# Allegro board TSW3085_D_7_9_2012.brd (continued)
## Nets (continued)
USB RESET: C50.1 SW2.2 U3.19(RESET)
N27288443: C95.1 J14.2(D-) U3.16(USBDM)
N27288567: FB26.2 R40.1 U3.20(VCC)
N27288614: C97.1 U3.4(VCCIO) U3.17(3V3OUT)
N27288630: C96.1 J14.3(D+) U3.15(USBDP)
N27836198: C152.1 C153.1 F2.2 FB20.2 Q1.4(S4) Q1.7(S7)
N28086696: C133.1 C163.1 C169.1 C234.1 C240.1 FB31.3 TP20.1(TP) U12.1(EN) U12.2(IN) U13.1(IN) U13.3(EN) U22.1(IN) U22.3(EN)
N28167010: C184.1 C197.2 L3.1 R277.1
N28167020: C184.2 C192.1 L4.1 R278.1
N28168739: C200.2 C205.1 L1.1 R280.1
N28168741: C205.2 C220.1 L2.1 R279.1
N28168902: C206.2 C221.1 R279.2 R303.1
N28168904: C206.1 C217.2 R280.2 R302.1
N30175128: C146.1 C244.1 C245.1 FB34.1 R128.2 R257.2 U13.5(OUT)
N30185572: C149.1 C246.1 C247.1 R127.1 R221.2 U22.5(OUT)
N31066293: C186.1 C198.2 R277.2 R296.1
N31066982: C186.2 C193.1 R278.2 R297.1
N33713354: C35.1 R43.1 R133.1
N33713380: C34.1 R43.2
N33713396: R133.2 U1.A1(LPF)
N33713852: R44.2 R45.1
N33713873: R44.1 U1.A33(BIASJ)
N33714300: JP3.2(PIN2) U1.B40(SLEEP)
N33806169: C259.1 R313.1
N33840412: C252.1 C253.1 C288.1 C290.1 R88.1 R118.2 U23.24(VCC_LO)
N33892115: C254.1 C255.1 C289.1 C291.1 R96.2 R115.2 U23.18(VCC_MOD)
N33970284: R12.2 R221.1 U22.4(NR/FB)
N33977043: R10.2 R257.1 U13.4(NR/FB)
N34062669: C132.2 C259.2 R174.1
N34111815: C113.1 U14.6(NR)
N34113396: R157.1 R159.2 U14.3(FB/SNS)
N34123238: FB35.1 R127.2 R128.1
N34242338: C119.1 U18.6(NR)
N34242397: R171.2 R176.1 U18.3(FB/SNS)
N34261747: R107.2 U7.3(\\P\/S)
N34261766: C175.1 C176.1 FB23.1 U7.2(VDD)
N34261843: C110.1 C251.1 C256.1 L5.1 R293.2
N34261894: R108.2 U7.4(A0) U7.22(A1)
N34318237: C107.1 C127.1 U16.42(CPOUT2)
N34318365: C59.1 U16.11(LDOBYP1)
N34318369: C52.1 U16.12(LDOBYP2)
N34318504: D1.1(ANODE) R8.1
N34318582: R11.2 U16.33(STATUS_LD)
N34318594: R9.2 U16.63(STATUS_CLKIN1)
N34318598: R8.2 U16.62(STATUS_CLKIN0)
N34318724: FB2.2 JP4.2(PIN2)
N34318773: C77.2 U16.37(OSCINN)
N34318798: C88.1 C102.1 C181.1 FB10.1 U16.17(VCC2) U16.18(VCC3)
N34318866: C87.1 C179.1 FB19.1 U16.64(VCC13)
N34318908: R274.2 Y1.2(\\E\D\)
N34318943: R70.2 R72.1 SJP5.2(PIN2) U26.1(CLKIN)
N34319037: C302.1 C303.1 FB8.1 U26.2(OE) U26.6(VDD3.3V)
N34319101: R61.2 R62.2 R273.2 Y1.1(VC)
N34319133: C63.1 C64.1 C65.1 FB2.1 R61.1 Y1.6(VDD)
N34319167: R54.1 Y1.4(OUT)
N34319169: R54.2 SJP5.3(PIN3)
N34319278: D5.1(ANODE) R9.1
N34319280: D4.1(ANODE) R11.1
N34319320: C89.1 C90.1 C99.1 C180.1 FB18.1 U16.47(VCC10) U16.52(VCC11) U16.57(VCC12)
N34319417: C86.1 C298.1 FB12.1 U16.41(VCC8)
N34319628: C78.2 U16.26(CLKIN1N/FBCLKINN/FINN)
N34337938: D3.1(ANODE) R40.2
N34338940: C8.1 FB26.1 U6.5(VOUT)
N34339153: SJP3.2(PIN2) U6.3(ON/O\F\F\)
N34340024: J14.4(ID) R117.1
N34341306: U4.35(IO14) U5.2(SO)
N34341363: R19.1 U3.3(D2) U4.43(IO2)
N34341376: R20.1 U3.11(D3) U4.18(IO26)
N34341390: R22.1 U3.9(D5) U4.19(IO25)
N34341426: R21.1 U3.2(D4) U4.44(IO3)
N34341471: R120.2 U5.7(H\O\L\D\)
N34341475: U4.34(IO15) U5.1(C\S\)
N34341497: SJP2.2(PIN2) U5.3(W\P\)
N34341585: R23.1 U3.10(D6) U4.23(IO21)
N34341705: R24.1 U3.6(D7) U4.22(IO22)
N34341779: R16.1 U3.1(D0) U4.2(IO4)
N34341783: R17.1 U3.5(D1) U4.42(IO1)
N34538813: SJP4.2(PIN2) U4.37(INPUT/GCLK1)
N34674333: C166.1 C167.1 FB30.1 L26.2 R150.2
N34674399: C165.1 FB31.1 L25.2 R148.2 U11.4(FB1)
N34674443: C166.2 R150.1 R153.2 U11.1(ADJ2)
N34674591: L25.1 U11.6(SW1)
N34674628: C145.1 C164.1 FB22.1 FB24.1 U12.4(OUT)
N34674653: R148.1 R151.2 U11.5(DEF_1)
N34674671: C162.1 U12.5(NR/FB)
N34674884: C299.2 R95.2 R104.1 U2.3(FB)
N34674886: C299.1 C305.1 FB28.1 L7.2 R104.2
N34674940: C215.1 U15.5(NR/FB)
N34674946: C306.1 C307.1 FB28.3 U15.1(EN) U15.2(IN)
N34708918: J13.175 R175.1
N34708920: J13.177 R177.1
N34708959: J13.21 R6.1
N34714738: J13.38 R25.2
N34714741: J13.40 R26.2
N34722561: J13.50 R28.2
N34722570: J13.52 R27.2
N34728902: J13.47 R1.1
N34729206: J13.51 R2.1
N34729215: J13.53 R3.1
N34729224: J13.59 R4.1
N34783131: C7.1 U6.4(BYP)
N34841492: Q1.3(G3) U21.4(GATE)
N278362830: D2.1(ANODE) R143.1
N343181311: C127.2 R89.1
N343181471: C177.2 R90.1
N346744130: L26.1 U11.10(SW2)

Pads without a net: J13 5 6 11 12 13 14 15 16 17 18 19 20 22 23 24 25 29 30 31 32 33 34 35 36 37 39 41 42 43 44 45 46 54 56 58 60 62 64 68 70 74 76 80 82 86 88 92 94 98 100 104 106 110 112 122 124 128 130 134 136 140 142 146 148 152 154 158 160 164 166 169 171; J14 1; J15 6 7 8; NOREF#22 1; NOREF#33 1; NOREF#43 1; NOREF#45 1; NOREF#46 1; NOREF#47 1; U1 A44; U3 8 12 13 14 22 23 24 27 28; U7 1 26 27 28 29 30 31 32; U16 3 4 5 7 8 9 13 14 21 22 31 32 39 40 49 50 51 55 56 58 59 60 61; U21 1 3; U26 3; Y1 5

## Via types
v1: diameter 0.508, hole 0.254, TOP to BOTTOM, 1602 vias
v2: diameter 0.254, hole 0.203, TOP to BOTTOM, 151 vias
v3: diameter 0.61, hole 0.305, TOP to BOTTOM, 221 vias
v4: diameter 0.914, hole 0.254, TOP to BOTTOM, 2 vias
v5: diameter 0.254, hole 0.152, TOP to BOTTOM, 42 vias
v6: diameter 0.559, hole 0.305, TOP to BOTTOM, 93 vias
v7: diameter 0.406, hole 0.203, TOP to BOTTOM, 39 vias
v8: diameter 0.762, hole 0.381, TOP to BOTTOM, 8 vias

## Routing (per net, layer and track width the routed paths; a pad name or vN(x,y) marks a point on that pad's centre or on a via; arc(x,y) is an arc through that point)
6VIN: length 5.3
  BOTTOM w0.254: J13.2 v1(9.88,100.99) ; J13.4 v1(12.57,100.49) ; J13.1 v1(3.83,100.99) ; J13.3 v1(6.45,100.49)
  vias: v1(2.92,102.88) v1(2.92,101.61) v1(3.91,102.97) v1(4.42,102.46) v1(5.05,101.96) v1(9.91,102.88) v1(10.77,102.97) v1(11.38,102.46) v1(12.04,102.08) v1(13.08,103.52) v1(15.62,106.69) v1(15.62,104.15) v1(16.89,107.33) v1(16.89,105.42) v1(16.89,103.52) v1(18.16,106.69) v1(18.16,104.15)
+1.2VCLK: length 0.5
  TOP w0.102: U1.A4 44,69.41
  TOP w0.152: 44,69.41 43.89,69.52 v2(43.89,69.65)
  vias: v1(65.66,30.23) v1(65.66,29.46) v1(65.91,28.57) v1(66.42,30.86) v1(66.42,29.97) v1(66.42,29.21) v1(66.8,28.57) v1(67.18,30.86) v1(67.18,29.97) v1(67.18,29.21) v2(41.27,75.06) v2(41.27,74.42) v2(41.78,74.55) v2(42.29,75.06) v2(42.29,74.55)
+1.2VD: length 6.9
  TOP w0.102: v5(40.87,70.43) 41,70.3 U1.A9 ; 41,59.54 41.02,59.52 41.02,59.23 ; U1.A25 41,60.5 ; U1.A28 42.8,60.5 ; 42.8,59.59 42.8,59.23
  TOP w0.127: 42.8,60.5 42.8,60.3
  TOP w0.152: v5(42.65,69.62) 42.65,69.35 U1.A6 ; 42.8,60.3 42.8,59.59 ; 41.02,59.23 41.02,58.93 40.82,58.72 v2(40.77,58.72) ; 41,60.5 41,59.54 ; v2(42.88,58.72) 42.8,58.85 42.8,59.23
  BOTTOM w0.254: C26.1 41,70.31 v5(40.87,70.43)
  vias: v1(36.14,25.6) v1(36.2,24.51) v1(36.58,23.88) v1(36.83,25.91) v1(36.83,25.27) v1(37.47,25.91) v1(37.47,25.27) v1(37.54,24.77) v1(37.8,24.26) v1(38.05,23.72) v1(38.1,25.91) v1(38.1,25.27) v1(38.86,75.06) v1(39.24,74.55) v1(39.88,74.93)
+1.2VDAC: length 2.1
  TOP w0.102: U1.A39 v5(47.98,64.95)
  BOTTOM w0.102: C17.1 47.09,67.35 v5(47.1,67.35)
  BOTTOM w0.254: C36.1 43.71,68.3 v5(43.71,68.38) v5(43.71,68.66) ; v5(47.1,62.55) 47.09,62.54 C19.1
  vias: v1(59.05,27.56) v1(59.05,26.8) v1(59.31,26.04) v1(59.82,27.56) v1(59.82,26.8) v1(60.07,26.04) v1(60.58,28.07) v1(60.58,27.18) v2(49.06,61.39) v2(49.06,60.38) v2(49.57,60.88) v2(50.08,61.39) v2(50.08,60.38)
+3.3V_MOD1:
  vias: v1(74.3,26.29) v1(74.68,26.92) v1(75.06,26.29) v1(75.44,26.92) v1(75.82,26.29) v1(76.2,26.92) v1(76.58,26.29) v1(76.96,26.92) v1(77.34,26.29) v1(77.6,65.05) v1(77.6,64.41) v1(77.6,63.65) v1(78.23,65.05) v1(78.23,64.41) v1(78.23,63.65)
+3.3V_MOD2:
  vias: v1(79.63,26.29) v1(80.01,26.92) v1(80.39,26.29) v1(80.77,26.92) v1(81.15,26.29) v1(81.53,26.92) v1(81.91,26.29) v1(82.3,26.92) v1(82.68,26.29) v1(102.64,69.62) v1(102.64,68.99) v1(103.4,70.26) v1(103.4,69.62) v1(103.4,68.99)
+3.3VA: length 1
  BOTTOM w0.305: C22.1 47.09,64.49 v5(47.09,64.35) v5(47.09,63.75) ; v5(47.09,65.54) 47.04,65.49 C20.1
  vias: v1(58.1,76.96) v2(46.42,62.25) v2(49.97,69.37) v2(49.97,68.35) v2(50.48,68.86) v2(50.99,69.37) v2(50.99,68.35) v3(48.26,17.91) v3(48.26,17.14) v3(48.26,16.26) v3(48.26,15.37) v3(49.28,17.91) v3(49.28,17.14) v3(49.28,16.26) v3(49.28,15.37) v5(47.09,66.75) v5(47.09,66.14) v5(47.09,63.14)
+3.3VCLK: length 2.6
  TOP w0.508: v3(76.71,124.33) v1(77.52,124.33)
  BOTTOM w0.508: v1(89.15,110.06) 89.15,110.39 v1(89.32,110.55) U4.29
  vias: v1(34.72,101.57) v1(35.28,101.45) v1(37.77,102.11) v1(38.33,102.67) v1(42.38,101.4) v1(43.25,94.81) v1(43.36,94.16) v1(43.69,116.36) v1(43.78,116.98) v1(48.2,110.05) v1(48.89,101.71) v1(49.98,108.27) v1(51.02,107.21) v1(51.07,103.84) v1(52.5,112.19) v1(52.95,104.21) v1(53.06,112.09) v1(53.54,104.14) v1(73.03,119.38) v1(82.89,106.17) v1(84.58,106.17) v1(85.85,102.23) v1(86.12,100.55) v1(88.14,117.35) v1(88.65,115.15) v1(89.15,117.35) v1(92.46,104.52) v1(93.6,117.48) v1(94.14,104.57) v1(97.54,124.08) v1(100.33,126.62) v1(100.71,110.74) v1(102.87,126.62) v1(105.41,126.62) v1(109.35,126.62) v2(42.7,101.73) v2(47.9,109.75) v2(48.64,102.01) v2(49.68,108) v2(50.75,106.93) v2(50.75,104.14) v3(90.32,117.3) v3(91.29,116.69) v3(99.95,107.44) v3(100.46,108.2) v3(100.56,109.6) v3(100.58,105.54) v3(100.58,104.78)
+3.3VD: length 10.7
  BOTTOM w0.152: C41.1 v5(42.49,68.66)
  BOTTOM w0.254: v2(38.5,64.9) 38.81,64.9 C43.1 ; C42.1 v2(42.5,61.25)
  BOTTOM w0.508: R46.2 v1(44.83,38.23)
  BOTTOM w0.762: JP3.1 JP2.1
  vias: v1(42.7,29.97) v1(42.7,29.29) v1(42.7,28.6) v1(42.7,27.89) v1(42.7,27.2) v1(43.31,30) v1(43.31,29.31) v1(43.31,28.63) v1(43.31,27.91) v1(43.31,27.23) v5(42.49,68.35)
+3.3VRF:
  vias: v1(77.72,17.78) v1(78.36,16.51) v1(78.36,15.24) v1(78.36,13.97) v1(78.36,12.7) v1(78.99,17.78) v1(79.63,16.51) v1(79.63,15.24) v1(79.63,13.97) v1(80.26,17.78) v1(81.53,17.78) v1(82.8,17.78) v1(107.62,55.4) v1(110.18,50.57) v1(113.18,55.4)
+3.6V: length 3
  TOP w0.305: L7.1 109.74,109.87 U2.1
+5V_MOD1:
  vias: v1(87,26.42) v1(87.38,27.05) v1(87.63,26.42) v1(88.01,27.05) v1(88.27,26.42) v1(88.65,27.05) v1(88.9,26.42) v1(89.28,27.05) v1(89.53,26.42) v1(91.19,59.74) v1(91.29,70) v1(94.21,59.71) v1(94.36,70)
+5V_MOD2:
  vias: v1(74.42,67.46) v1(74.42,66.83) v1(75.06,67.46) v1(75.06,66.83) v1(75.69,67.46) v1(75.69,66.83) v1(92.33,26.42) v1(92.71,27.05) v1(92.96,26.42) v1(93.34,27.05) v1(93.6,26.42) v1(93.98,27.05) v1(94.23,26.42) v1(94.62,27.05) v1(94.87,26.42) v1(102.36,75.08) v1(102.36,74.45) v1(102.36,73.81) v1(103,75.08) v1(103,74.45) v1(103,73.81)
+5VA_MOD: length 0.9
  TOP w0.305: 86.61,12.19 86.05,11.63 U18.2
  vias: v1(88.77,17.91) v1(88.77,16.89) v1(89.92,17.91) v1(89.92,16.89) v1(91.06,17.91) v1(91.06,16.89) v1(92.2,17.91) v1(92.2,16.89) v1(93.34,17.91) v1(93.34,16.89) v1(94.62,17.91) v1(94.62,16.89) v1(105.97,50.04)
+6V: length 9.4
  TOP w0.305: 36.96,15.92 C237.1 ; 36.96,15.92 v2(38.43,15.92) ; 36.96,15.92 36.96,15.62 37.17,15.42 U11.3 ; v3(115.72,109.04) 115.54,109.22 v2(115.07,109.22) ; v1(84.43,8.08) 84.75,8.4 U18.5 ; 76.96,7.87 76.53,8.31 U14.7 ; 86.49,7.87 86.05,8.31 U18.7 ; U14.5 75.23,8.55 v1(74.8,8.13) ; v1(42.42,14.91) 42.41,14.92 U11.7
  TOP w0.508: C172.1 v1(83.06,7.75)
  vias: v1(32.74,16.15) v1(32.77,15.62) v1(33.48,16.59) v1(33.66,15.62) v1(34.62,16.21) v1(34.67,15.62) v1(35.69,15.62) v1(35.76,16.1) v1(36.7,15.62) v1(36.78,16.13) v1(72.9,7.24) v1(73.41,6.48) v1(79.04,7.49) v1(79.04,6.88) v1(79.65,7.49) v1(79.65,6.91) v1(88.9,7.47) v1(88.9,6.86) v1(89.51,7.47) v1(89.51,6.88) v1(93.32,11.29) v1(96.74,12.88) v1(96.74,11.87) v1(103.78,118.03) v1(106.81,116.21) v2(38.43,15.42) v2(41.45,14.91) v2(41.48,15.93) v2(115.07,108.57) v3(94.61,11.82) v3(95.54,11.15) v3(105.66,112.52) v3(107.06,118.75) v3(107.06,117.48) v3(107.7,118.11) v3(108.61,118.77) v3(108.64,117.45) v3(116.08,108.48) v3(116.64,108.92) v3(117.3,108.51)
GNDA: length 163.4
  TOP w0.152: v1(63.12,28.83) C238.2 v1(63.88,28.83) ; U3.7 97.21,117.93 v1(97.16,117.98)
  TOP w0.254: U1.B33 46.45,63.11 v2(46.43,63.04) 46.45,63.08 U1.B32 ; v1(95.66,65.91) 95.47,65.72 95.38,65.72 95.36,65.7 U23.17 ; U23.8 92.01,62.09 v1(91.82,61.9) ; U1.B39 v2(46.45,66.91) ; U1.B38 v2(46.45,66.28)
  TOP w0.305: v1(93.52,64.19) 94.01,63.7 ; v1(93.52,64.19) 93.51,64.17 U23.11 ; v1(93.52,64.19) 93.53,64.2 U23.14 ; 94.01,63.7 U23.13 ; 94.01,63.7 U23.12 ; v1(84.4,12.17) 84.75,11.82 U18.4 ; v1(113.92,109.8) 113.98,109.87 U2.6 ; v2(112.77,109.22) 113.89,109.22 v1(113.92,109.25) ; v1(93.52,65.71) 93.51,65.72 U23.20 ; v1(93.52,65.71) 93.53,65.7 U23.17 ; v1(93.52,65.71) 93.98,66.17 93.98,66.59 94.01,66.62 U23.19 ; v1(81.66,62.89) 81.08,63.47 R313.2 ; v5(93.52,62.71) 93.52,62.1 v1(93.73,61.9) ; v1(61.98,10.41) U13.2 v1(60.58,10.41) ; U11.8 v3(40.36,15.42) v1(40.33,15.42) U11.11 ; v1(75.5,10.66) 75.23,10.93 U14.4 75.23,11.9 v1(74.93,12.19) ; U22.2 v1(68.83,10.29) ; U23.23 92.01,65.72 v1(92,65.71) 91.99,65.7 U23.2 ; U23.5 91.99,64.2 v1(92,64.19) 92.01,64.17 U23.8 ; U23.15 93.53,64.7 v1(93.52,64.69)
  TOP w0.381: v1(70.53,123.28) U26.4 v1(73.26,123.28) ; v1(99.75,14.68) U21.2 v1(98.65,14.66)
  TOP w0.508: C254.2 v1(98.02,67.74) ; v1(101.71,68.24) v3(100.84,68.24) v1(100.84,67.23) ; v1(60.71,15.11) v3(61.29,15.11) C244.2 ; D5.2 v1(27.33,100.13) ; C196.1 v1(62.59,73.43) ; C245.2 v1(61.72,16.41) ; v1(66.29,11.3) v3(66.29,10.72) C240.2 ; C170.2 v1(56.52,25.53) ; v3(68.3,14.86) v1(67.69,14.86) ; R200.2 v1(94.21,56.67) ; C191.2 v1(62.59,70.41) ; v1(60.2,13.34) v3(60.93,13.34) C146.2 v1(60.96,12.47) ; C174.2 v1(84.96,14.61) ; D4.2 v1(27.36,102.41) ; R6.2 v1(7.34,97.66) ; v1(57.02,26.8) C243.2 ; C149.2 v1(67.18,13.08) ; C199.1 v1(73.76,56.84) ; v1(70.36,6.86) v3(71.12,6.86) ; C171.2 v1(74.17,16.64) ; C172.2 v1(83.06,9.78) ; D1.2 v1(27.36,97.84) ; v3(75.41,14.99) v1(74.8,14.99) ; C120.2 v1(89.28,10.54) ; R198.2 v1(94.34,73.05) ; v1(54.58,12.5) v3(54.58,13.39) U12.3 v1(54.58,14.4) ; C194.2 v1(73.79,70.43) ; v1(78.77,9.8) v3(79.35,9.8) C114.2 v1(79.38,10.41) ; v1(74.3,13.21) v1(74.3,13.72) ; R12.1 v1(72.01,8.61) ; C167.2 v3(38.4,19.3) ; C169.2 v3(59.31,10.72) v1(59.31,11.3) ; D2.2 v1(90.65,7.16) ; C255.2 v1(97.03,67.77) ; C173.2 v1(84.28,16.38) ; C233.2 v1(34.62,25.6) ; C218.2 v1(73.79,59.89) ; C219.2 v1(62.59,59.87) ; C147.2 v1(55.88,23.75)
  L2_GND w0.305: 93.73,41.48 93.73,41.15 93.47,40.89
  BOTTOM w0.102: 45.92,68.02 C48.2 ; v6(45.3,67.4) 45.21,67.48 ; 46.45,66.18 v2(46.45,66.28)
  BOTTOM w0.152: R137.1 97.14,61.71 v1(97.28,61.85)
  BOTTOM w0.254: C21.2 46.36,66.8 45.97,66.8 45.72,66.55 45.45,66.55 v6(45.3,66.4) 45.57,66.12 46.42,66.12 C23.2 46.45,66.18 ; C49.2 v5(45.21,67.89) 45.21,67.48 ; v6(44.3,67.4) 44.06,67.16 C36.2 ; C42.2 41.74,61.96 v6(41.3,62.4) ; v6(40.3,65.4) 40.23,65.33 40.23,65.1 40.01,64.92 C43.2 ; v6(45.3,67.4) 45.92,68.02
  BOTTOM w0.305: 12.95,60.07 12.87,59.98 J13.126 10.2,59.98 v1(9.78,59.56) ; v1(9.91,75.18) 10.2,75.48 J13.84 13.16,75.48 13.21,75.44 ; J13.83 v1(4.16,75.48) ; J13.101 v1(4.12,70.98) ; 12.95,58.67 12.76,58.48 J13.132 10.09,58.48 v1(9.53,57.91) ; 13.21,77.09 13.1,76.98 J13.78 9.67,76.98 9.4,76.71 ; v1(9.65,51.05) 9.73,50.98 J13.162 12.91,50.98 12.95,50.93 ; v6(41.3,67.4) 41,67.7 C26.2 ; 12.95,79.88 12.85,79.98 J13.66 10.13,79.98 v1(9.78,79.63) ; J13.7 v1(4.07,99.49) ; J13.89 v1(4.1,73.98) ; v6(45.3,63.4) 45.71,63.8 C5.2 ; v6(45.3,65.4) 45.37,65.33 C20.2 ; C41.2 42.49,67.59 v6(42.3,67.4) ; J13.161 3.94,50.98 3.43,50.47 v1(3.43,50.42) ; J13.65 v1(4.11,79.98) ; 10.03,55.5 10.05,55.48 J13.144 12.81,55.48 12.83,55.5 ; v6(45.3,62.4) 45.47,62.23 C6.2 ; J13.137 v1(4.1,56.98) ; J13.149 v1(4.04,53.98) ; J13.77 v1(4.17,76.98) ; J13.9 v1(6.28,98.99) ; 9.4,56.77 9.61,56.98 J13.138 12.62,56.98 v1(12.7,56.9) ; 12.83,53.98 12.82,53.98 J13.150 10.28,53.98 v1(9.4,54.86) ; v6(45.3,64.4) 45.44,64.54 C22.2 ; J13.156 12.34,52.48 v1(13.08,53.21) ; 11.3,45.72 11.35,45.77 J13.180 v1(10.25,46.47) ; 12.83,68.58 12.22,67.98 J13.114 v1(10.32,67.98) ; J13.71 v1(4.14,78.48) ; v1(13.08,49.66) 12.9,49.47 J13.168 9.85,49.47 9.78,49.4 ; J13.143 v1(4.07,55.48) ; J13.174 v1(10.29,47.97) ; J13.119 v1(4.12,66.47) ; 9.4,78.11 9.78,78.48 J13.72 13.71,78.48 13.84,78.61 ; J13.8 v1(12.48,99.49) ; 9.78,69.47 9.79,69.48 J13.108 13.07,69.48 13.08,69.47 ; J13.107 v1(4.13,69.48) ; J13.179 v1(4.16,46.47) ; J13.10 v1(10.26,98.99) ; J13.131 v1(4.05,58.48) ; v1(12.95,73.91) 12.89,73.98 J13.90 ; J13.113 v1(4.07,67.98) ; 9.78,70.99 9.79,70.98 J13.102 12.3,70.98 v1(12.83,71.5) 12.83,71.94 12.28,72.48 J13.96 9.99,72.48 9.78,72.26 ; J13.120 10.85,66.47 10.59,66.22 v1(10.59,65.79) ; J13.167 v1(4.15,49.47) ; J13.95 v1(4.13,72.48) ; J13.125 v1(4.03,59.98) ; J13.155 v1(4.09,52.48) ; J13.173 v1(4.12,47.97)
  BOTTOM w0.508: C47.2 v1(44.32,36.7) ; R45.2 v1(46.1,53.57) ; C154.2 v1(97.76,12.37) v1(97.76,12.88) ; C7.2 C8.2 ; C152.2 v1(90.35,4.62)
  vias: v1(0.84,37.72) v1(0.89,84.07) v1(0.89,81.79) v1(0.89,77.98) v1(0.89,74.17) v1(0.89,70.36) v1(0.89,66.55) v1(0.89,62.74) v1(0.89,58.93) v1(0.89,55.12) v1(0.89,51.31) v1(0.89,47.5) v1(0.94,41.68) v1(1.02,110.49) v1(1.02,106.68) v1(1.02,102.87) v1(1.02,99.06) v1(1.02,95.25) v1(1.02,91.44) v1(1.02,87.63) v1(1.02,44.96) v1(3.18,108.59) v1(3.76,105) v1(3.81,112.4) v1(3.81,104.01) v1(4.45,34.92) v1(5.08,113.67) v1(5.08,105.03) v1(5.08,104.01) v1(5.08,39.37) v1(5.33,107.32) v1(5.89,84.23) v1(5.92,82.55) v1(6.1,63.5) v1(7.62,111.76) v1(8,59.26) v1(8.23,103.02) v1(8.26,102.11) v1(8.26,101.24) v1(8.23,98.81) v1(8.26,97.84) v1(8.26,96.84) v1(8.26,95.96) v1(8.26,92.46) v1(8.26,91.49) v1(8.26,90.49) v1(8.26,89.54) v1(8.26,88.47) v1(8.26,86.16) v1(8.26,85.22) v1(8.26,84.3) v1(8.26,82.5) v1(8.26,81.25) v1(8.26,78.84) v1(8.26,76.25) v1(8.26,74.83) v1(8.26,69.52) v1(8.26,66.17) v1(8.26,65.21) v1(8.26,64.29) v1(8.26,57.53) v1(8.26,55.88) v1(8.26,51.51) v1(8.26,50.67) v1(8.26,48.59) v1(8.26,45.85) v1(8.26,45.21) v1(8.23,44.27) v1(8.26,34.92) v1(8.28,71.48) v1(8.28,61.98) v1(8.28,61.26) v1(9.53,44.58) v1(10.74,105) v1(10.74,103.99) v1(11.02,29.77) v1(11.43,118.11) v1(11.38,104.5) v1(11.43,44.58) v1(12.01,105) v1(12.01,103.99) v1(12.07,34.92) v1(12.52,98.22) v1(12.7,111.76) v1(12.73,87.43) v1(12.7,39.37) v1(13.21,44.45) v1(13.34,116.21) v1(13.97,41.27) v1(14.61,114.94) v1(15.11,32) v1(15.24,118.11) v1(15.24,40.01) v1(15.49,29.77) v1(15.88,116.21) v1(15.88,34.92) v1(16.21,86.49) v1(16.51,41.27) v1(17.42,89.71) v1(17.78,111.76) v1(17.78,39.37) v1(19.05,118.11) v1(19.69,87.63) v1(19.69,85.09) v1(19.69,34.92) v1(20.04,29.74) v1(20.95,86.36) v1(21.59,108.59) v1(21.59,106.05) v1(22.23,87.63) v1(22.23,85.09) v1(22.23,45.09) v1(22.86,111.76) v1(22.86,107.32) v1(22.86,39.37) v1(23.5,43.81) v1(23.5,34.92) v1(23.75,94.67) v1(24.13,108.59) v1(24.13,106.05) v1(24.13,40.64) v1(24.61,29.77) v1(24.77,92.71) v1(24.77,90.17) v1(24.77,45.09) v1(25.4,118.11) v1(25.4,39.37) v1(26.04,110.49) v1(26.04,91.44) v1(26.67,40.64) v1(27.3,132.08) v1(27.3,128.27) v1(27.3,124.46) v1(27.3,120.65) v1(27.3,116.84) v1(27.3,109.22) v1(27.3,92.71) v1(27.3,90.17) v1(27.3,34.92) v1(27.3,31.75) v1(27.3,27.94) v1(27.3,24.13) v1(27.3,20.32) v1(27.3,15.88) v1(27.3,13.97) v1(27.3,10.8) v1(27.3,7.62) v1(27.3,5.71) v1(27.94,130.81) v1(27.94,117.48) v1(27.94,111.76) v1(28.42,39.4) v1(28.57,110.49) v1(29.21,129.54) v1(29.21,116.21) v1(29.21,29.84) v1(29.21,27.3) v1(29.21,9.53) v1(29.21,6.99) v1(29.59,90.04) v1(29.59,87.5) v1(29.85,22.86) v1(29.85,20.32) v1(30.48,130.81) v1(30.48,117.48) v1(30.48,28.57) v1(30.48,8.25) v1(30.86,88.77) v1(31.04,41.33) v1(31.12,34.92) v1(31.12,32.38) v1(31.12,21.59) v1(31.75,125.73) v1(31.75,123.19) v1(31.75,29.84) v1(31.75,27.3) v1(31.75,13.97) v1(31.75,11.43) v1(31.75,9.53) v1(31.75,6.99) v1(31.75,0.64) v1(32.13,116.21) v1(32.13,114.17) v1(32.13,90.04) v1(32.13,87.5) v1(32.38,117.98) v1(32.38,33.66) v1(32.38,22.86) v1(32.38,20.32) v1(32.64,107.95) v1(32.64,40.39) v1(33.02,124.46) v1(33.02,46.35) v1(33.02,12.7) v1(33.66,34.92) v1(33.66,32.38) v1(33.78,42.04) v1(34.16,119.76) v1(34.29,125.73) v1(34.29,123.19) v1(34.29,45.09) v1(34.29,13.97) v1(34.29,11.43) v1(34.54,97.28) v1(34.62,17.78) v1(34.67,94.49) v1(34.8,109.86) v1(34.92,132.72) v1(34.93,105.33) v1(35.05,99.06) v1(35.36,43.54) v1(35.56,46.35) v1(35.74,17.12) v1(35.81,121.29) v1(35.81,112.78) v1(36.2,0.64) v1(36.45,107.82) v1(36.58,134.49) v1(36.58,131.06) v1(36.68,11.48) v1(36.78,17.12) v1(36.83,4.45) v1(36.83,1.91) v1(37.09,107.49) v1(37.34,122.81) v1(37.34,97.28) v1(37.34,94.62) v1(37.44,45.47) v1(37.95,19.86) v1(37.95,18.72) v1(37.97,119.76) v1(38.1,112.9) v1(38.07,21.36) v1(38.1,3.17) v1(38.73,124.21) v1(38.73,77.72) v1(38.84,19.86) v1(38.84,18.72) v1(39.24,115.57) v1(39.24,103) v1(39.27,77.08) v1(39.37,4.45) v1(39.37,1.91) v1(39.53,16.22) v1(39.53,15.42) v1(39.53,14.62) v1(39.62,121.41) v1(39.75,76.58) v1(40.01,49.53) v1(40.01,46.99) v1(40.01,41.91) v1(40.14,111.03) v1(40.33,16.22) v1(40.33,14.62) v1(40.39,125.86) v1(40.39,115.06) v1(40.64,0.64) v1(40.7,98.49) v1(40.77,133.98) v1(40.79,96.93) v1(41.15,131.57) v1(41.15,122.94) v1(41.27,129.29) v1(41.27,127) v1(41.27,76.58) v1(41.27,48.26) v1(41.4,97.28) v1(41.66,113.79) v1(41.81,77.08) v1(42.15,98.44) v1(42.33,113.2) v1(42.29,77.6) v1(42.55,121.29) v1(42.55,49.53) v1(42.55,46.99) v1(42.55,45.09) v1(42.67,133.86) v1(42.93,124.59) v1(43.81,120.02) v1(43.94,131.57) v1(43.94,130.05) v1(43.94,128.27) v1(43.94,126.11) v1(44.35,96.24) v1(45.09,127) v1(45.09,124.46) v1(45.09,121.29) v1(45.09,118.75) v1(45.21,133.98) v1(45.72,86.61) v1(45.72,84.07) v1(45.72,0.64) v1(45.8,33.59) v1(46.36,125.73) v1(46.94,33.59) v1(46.97,96.38) v1(46.99,85.34) v1(47.12,108.97) v1(47.35,9.45) v1(47.5,123.06) v1(47.5,120.14) v1(47.5,117.6) v1(47.62,127) v1(47.62,124.46) v1(47.62,4.45) v1(47.62,1.91) v1(48.21,33.59) v1(48.26,86.61) v1(48.26,84.07) v1(48.89,107.19) v1(48.89,74.3) v1(48.89,73.28) v1(48.89,3.17) v1(49.14,98.54) v1(49.28,134.49) v1(49.28,124.84) v1(49.4,130.94) v1(50.04,120.02) v1(50.08,113.02) v1(50.16,122.05) v1(50.16,117.48) v1(50.16,44.45) v1(50.16,41.91) v1(50.16,4.45) v1(50.16,1.91) v1(50.42,125.98) v1(50.57,59.03) v1(50.67,114.48) v1(50.76,113.88) v1(50.8,52.07) v1(50.8,49.53) v1(50.8,0.64) v1(51.05,132.72) v1(51,33.59) v1(51.26,77.11) v1(51.44,43.18) v1(51.63,61.26) v1(51.63,60.5) v1(51.94,123.95) v1(51.89,100.08) v1(52.07,120.65) v1(52.07,118.11) v1(52.07,62.48) v1(52.13,60.88) v1(52.07,50.8) v1(52.12,33.59) v1(52.2,127.64) v1(52.26,113.73) v1(52.32,65.02) v1(52.4,97.82) v1(52.6,110.43) v1(52.64,61.26) v1(52.64,60.5) v1(52.7,44.45) v1(52.7,41.91) v1(53.09,100.08) v1(53.09,90.42) v1(53.09,87.88) v1(53.06,20.5) v1(53.06,19.74) v1(53.06,18.97) v1(53.34,119.38) v1(53.34,61.85) v1(53.34,59.82) v1(53.34,52.07) v1(53.34,49.53) v1(53.29,33.59) v1(53.85,71.76) v1(53.82,20.5) v1(53.82,19.74) v1(53.82,18.97) v1(53.98,133.98) v1(53.98,129.41) v1(53.98,125.73) v1(54.09,108.93) v1(54.36,89.15) v1(54.48,65.28) v1(54.48,58.04) v1(54.61,120.65) v1(54.61,118.11) v1(54.61,101.85) v1(54.58,20.5) v1(54.58,19.74) v1(54.58,18.97) v1(54.74,72.64) v1(54.76,0.71) v1(55.25,132.72) v1(55.25,66.55) v1(55.25,64.01) v1(55.25,54.61) v1(55.25,37.46) v1(55.25,34.92) v1(55.35,20.5) v1(55.35,19.74) v1(55.35,18.97) v1(55.37,100.08) v1(55.5,131.06) v1(55.47,97.82) v1(55.63,90.42) v1(55.63,87.88) v1(55.88,73.28) v1(56.01,127.89) v1(56.01,68.58) v1(56.01,61.72) v1(56.13,57.02) v1(56.11,20.5) v1(56.11,19.74) v1(56.11,18.97) v1(56.28,109.67) v1(56.26,59.82) v1(56.39,100.71) v1(56.39,70.61) v1(56.52,133.98) v1(56.52,53.34) v1(56.52,36.2) v1(57.02,110.97) v1(57.28,132.84) v1(57.4,73.28) v1(57.66,129.54) v1(57.66,102.11) v1(57.78,98.55) v1(57.78,34.92) v1(57.91,70.61) v1(58.04,96.27) v1(58.04,93.73) v1(58.17,59.69) v1(58.17,57.02) v1(58.42,136.53) v1(58.42,0.64) v1(58.55,110.74) v1(58.67,73.28) v1(58.8,99.57) v1(58.93,83.57) v1(58.93,81.03) v1(59.16,13.89) v1(59.18,103.38) v1(59.31,95) v1(59.44,70.61) v1(59.69,74.93) v1(59.69,73.28) v1(59.69,68.96) v1(59.69,67.44) v1(59.69,62.99) v1(59.69,60.96) v1(59.69,56.9) v1(59.69,54.99) v1(59.84,114.33) v1(59.82,76.58) v1(60.2,82.3) v1(60.33,53.59) v1(60.58,96.27) v1(60.58,93.73) v1(60.96,4.45) v1(60.96,1.91) v1(61.09,73.66) v1(61.09,70.23) v1(61.34,60.07) v1(61.34,56.64) v1(61.47,83.57) v1(61.47,81.03) v1(61.59,68.58) v1(61.59,66.04) v1(61.8,125.68) v1(61.85,117.6) v1(62.1,134.37) v1(62.1,130.81) v1(62.23,3.17) v1(62.23,0.64) v1(62.48,76.45) v1(62.61,136.53) v1(62.61,56.82) v1(62.61,42.67) v1(62.61,39.62) v1(62.61,27.69) v1(62.61,26.8) v1(62.87,67.31) v1(62.87,64.77) v1(62.87,62.23) v1(63.12,104.27) v1(63.25,100.58) v1(63.37,53.59) v1(63.37,27.18) v1(63.5,4.45) v1(63.5,1.91) v1(63.63,88.77) v1(63.63,86.23) v1(63.75,108.71) v1(63.78,126.26) v1(63.88,132.59) v1(64.01,73.79) v1(64.01,30.23) v1(64.13,70.1) v1(64.13,68.58) v1(64.13,66.04) v1(64.13,63.5) v1(64.13,60.2) v1(64.13,56.52) v1(64.9,119) v1(64.9,117.6) v1(64.9,87.5) v1(65.05,120.02) v1(65.02,102.49) v1(65.02,8.89) v1(65.28,76.45) v1(65.46,125.27) v1(65.41,70.1) v1(65.41,64.77) v1(65.41,62.23) v1(65.41,50.8) v1(65.41,48.26) v1(65.41,43.18) v1(65.41,40.64) v1(65.56,98.17) v1(65.53,73.79) v1(65.53,56.52) v1(65.66,60.07) v1(66.04,0.64) v1(66.17,88.77) v1(66.17,86.23) v1(66.55,117.32) v1(66.68,133.98) v1(66.68,73.46) v1(66.68,70.41) v1(66.68,59.87) v1(66.68,56.82) v1(66.68,49.53) v1(66.68,41.91) v1(66.8,53.59) v1(67.31,95.25) v1(67.31,68.58) v1(67.31,66.04) v1(67.56,76.45) v1(67.82,128.52) v1(67.82,126.75) v1(67.82,124.84) v1(67.79,123.77) v1(67.79,118.82) v1(67.94,132.72) v1(67.94,130.3) v1(67.94,50.8) v1(67.94,48.26) v1(67.94,43.18) v1(67.94,40.64) v1(68.2,73.79) v1(68.2,70.1) v1(68.2,60.2) v1(68.2,56.77) v1(68.45,136.53) v1(68.45,104.9) v1(68.45,102.36) v1(68.58,93.35) v1(68.58,90.81) v1(68.58,67.31) v1(68.71,16.13) v1(69.22,133.98) v1(69.22,131.57) v1(69.19,121.72) v1(69.47,120.47) v1(69.47,114.55) v1(69.6,60.2) v1(69.6,56.52) v1(69.72,103.63) v1(69.85,92.08) v1(69.85,68.58) v1(69.85,66.04) v1(70.48,128.91) v1(70.48,113.03) v1(70.48,110.49) v1(70.48,34.29) v1(70.48,31.75) v1(70.48,24.77) v1(70.48,22.22) v1(70.48,0.64) v1(70.61,132.84) v1(70.61,127.38) v1(70.61,125.35) v1(70.74,73.46) v1(70.74,70.41) v1(70.74,59.87) v1(70.74,56.82) v1(70.74,53.72) v1(70.84,120.47) v1(70.99,104.9) v1(70.99,102.36) v1(70.99,76.45) v1(71.12,93.35) v1(71.12,90.81) v1(71.75,114.55) v1(71.75,111.76) v1(71.75,64.77) v1(71.75,62.23) v1(71.75,33.02) v1(71.75,23.49) v1(72.01,56.52) v1(72.26,60.2) v1(72.39,4.45) v1(72.39,1.91) v1(73.03,118.36) v1(73.03,113.03) v1(73.03,110.49) v1(73.03,63.5) v1(73.03,47.62) v1(73.03,45.09) v1(73.03,34.29) v1(73.03,31.75) v1(73.03,24.77) v1(73.03,22.22) v1(73.41,115.57) v1(73.48,121.06) v1(73.66,136.53) v1(73.66,3.17) v1(73.79,73.46) v1(73.79,53.59) v1(74.04,76.45) v1(74.3,64.77) v1(74.3,62.23) v1(74.3,46.35) v1(74.3,40.64) v1(74.3,38.1) v1(74.6,120.75) v1(74.8,134.49) v1(74.93,130.81) v1(74.93,56.52) v1(74.93,4.45) v1(74.93,1.91) v1(75.18,74.55) v1(75.5,9.66) v1(75.56,60.83) v1(75.56,47.62) v1(75.56,45.09) v1(75.56,39.37) v1(75.69,58.42) v1(75.82,55.63) v1(75.82,0.64) v1(75.95,122.94) v1(75.95,121.92) v1(76.07,71.88) v1(76.2,51.44) v1(76.2,10.16) v1(76.58,132.59) v1(76.58,75.06) v1(76.58,59.18) v1(76.58,57.53) v1(76.58,55.24) v1(76.71,53.72) v1(76.84,76.33) v1(76.84,40.64) v1(76.84,38.1) v1(76.9,10.66) v1(76.9,9.66) v1(76.96,6.73) v1(77.14,122.81) v1(77.09,61.47) v1(77.34,119.38) v1(77.47,136.53) v1(77.47,102.23) v1(77.47,99.7) v1(77.47,50.16) v1(77.85,75.06) v1(77.77,3.23) v1(78.36,55.24) v1(78.49,72.64) v1(78.49,71.25) v1(78.49,59.18) v1(78.49,57.53) v1(78.61,124.46) v1(78.61,120.78) v1(78.74,100.97) v1(78.74,61.47) v1(78.74,51.44) v1(79.38,133.98) v1(79.88,125.73) v1(80.01,127.76) v1(80.01,102.23) v1(80.01,99.7) v1(80.01,59.18) v1(80.01,57.53) v1(80.39,122.56) v1(80.52,130.3) v1(80.52,72.77) v1(80.52,71.12) v1(80.65,132.72) v1(81.03,55.37) v1(81.15,89.28) v1(81.15,86.74) v1(81.28,68.71) v1(81.28,66.17) v1(81.28,64.9) v1(81.28,37.46) v1(81.28,34.92) v1(81.28,0.64) v1(81.53,61.34) v1(81.53,53.59) v1(81.66,131.57) v1(81.66,74.93) v1(81.79,58.42) v1(81.91,136.53) v1(81.91,133.98) v1(81.91,124.08) v1(81.91,48.26) v1(81.91,45.72) v1(82.17,65.15) v1(82.17,55.88) v1(82.42,88.01) v1(82.42,60.58) v1(82.55,73.79) v1(82.55,36.2) v1(82.8,128.65) v1(82.8,126.11) v1(82.89,105.37) v1(82.93,62.61) v1(83.06,76.45) v1(83.19,57.28) v1(83.19,46.99) v1(83.57,64.77) v1(83.69,133.6) v1(83.69,89.28) v1(83.69,86.74) v1(83.69,70.23) v1(83.82,125.73) v1(83.82,123.19) v1(83.82,67.31) v1(83.82,37.46) v1(83.82,34.92) v1(83.95,62.61) v1(84.12,3.23) v1(84.33,59.31) v1(84.33,13.46) v1(84.45,48.26) v1(84.45,45.72) v1(84.52,100.55) v1(84.58,105.16) v1(84.84,102.23) v1(84.96,53.72) v1(85.02,10.53) v1(85.02,9.53) v1(85.09,124.46) v1(85.09,57.28) v1(85.09,0.64) v1(85.22,66.47) v1(85.19,63.42) v1(85.32,111.8) v1(85.39,5.31) v1(85.37,4.57) v1(85.72,10.03) v1(86.23,59.05) v1(86.23,56.26) v1(86.36,136.53) v1(86.36,125.73) v1(86.36,123.19) v1(86.43,10.53) v1(86.43,9.53) v1(86.74,76.45) v1(86.87,93.73) v1(87,51.44) v1(87,40.64) v1(87,38.1) v1(87.12,66.8) v1(87.12,63.12) v1(87.17,69.57) v1(87.25,62.41) v1(87.5,54.99) v1(87.63,134.37) v1(87.63,130.68) v1(87.76,57.53) v1(87.76,53.47) v1(88.14,118.36) v1(88.19,69.6) v1(88.21,66.47) v1(88.27,63.45) v1(88.27,50.16) v1(88.27,39.37) v1(88.27,0.64) v1(88.65,76.07) v1(88.9,56.39) v1(89.15,118.36) v1(89.23,69.54) v1(89.41,132.72) v1(89.41,61.47) v1(89.41,54.1) v1(89.53,51.44) v1(89.53,40.64) v1(89.53,38.1) v1(89.79,62.74) v1(89.92,58.67) v1(90.04,71.12) v1(90.12,111.8) v1(90.12,100.55) v1(90.17,136.53) v1(90.17,110.11) v1(90.17,59.69) v1(90.17,57.66) v1(90.3,72.14) v1(90.3,68.99) v1(90.3,56.26) v1(90.55,6.22) v1(90.81,97.16) v1(90.81,94.62) v1(90.81,89.54) v1(90.81,87) v1(90.81,76.84) v1(90.81,61.98) v1(90.81,54.1) v1(91.19,56.67) v1(91.31,73.05) v1(91.44,0.64) v1(91.57,53.47) v1(92,65.2) v1(92,64.69) v1(92.08,95.89) v1(92.08,88.27) v1(92.33,54.1) v1(92.46,122.34) v1(92.46,103.51) v1(92.51,65.71) v1(92.51,65.2) v1(92.51,64.69) v1(92.51,64.19) v1(92.71,78.74) v1(93.01,65.71) v1(93.01,65.2) v1(93.01,64.69) v1(93.01,64.19) v1(93.34,133.35) v1(93.34,130.81) v1(93.34,97.16) v1(93.34,94.62) v1(93.34,89.54) v1(93.34,87) v1(93.34,54.74) v1(93.34,47.62) v1(93.34,45.09) v1(93.52,65.2) v1(93.57,7.04) v1(93.85,79.88) v1(94.14,108.57) v1(94.23,76.45) v1(94.62,132.08) v1(94.62,62.87) v1(94.62,61.98) v1(94.62,46.35) v1(94.74,122.68) v1(94.74,121.67) v1(94.74,120.65) v1(94.74,119.63) v1(94.74,118.62) v1(94.74,117.6) v1(94.74,116.46) v1(94.74,115.44) v1(94.74,114.43) v1(94.74,67.82) v1(95,53.47) v1(95.25,72.14) v1(95.25,57.66) v1(95.25,40.64) v1(95.25,38.1) v1(95.38,68.99) v1(95.38,59.82) v1(95.5,80.01) v1(95.5,69.98) v1(95.5,58.8) v1(95.63,71.12) v1(95.88,133.35) v1(95.88,130.81) v1(95.88,47.62) v1(95.88,45.09) v1(96.27,80.9) v1(96.52,125.1) v1(96.52,66.55) v1(96.52,39.37) v1(96.52,0.64) v1(96.77,58.55) v1(96.93,64.16) v1(97.03,136.53) v1(97.16,78.11) v1(97.16,33.66) v1(97.16,31.11) v1(97.16,22.22) v1(97.16,19.68) v1(97.54,76.45) v1(97.66,82.17) v1(97.79,40.64) v1(97.79,38.1) v1(97.94,66.19) v1(97.92,63.88) v1(97.92,53.98) v1(98.17,57.78) v1(98.3,79.25) v1(98.3,61.09) v1(98.43,32.38) v1(98.43,20.95) v1(98.55,108.2) v1(99.06,67.74) v1(99.06,53.34) v1(99.44,80.39) v1(99.44,66.55) v1(99.44,63.88) v1(99.44,57.15) v1(99.69,61.09) v1(99.69,33.66) v1(99.69,31.11) v1(99.69,22.22) v1(99.69,19.68) v1(99.95,136.53) v1(100.33,88.9) v1(100.33,86.36) v1(100.33,42.55) v1(100.33,40.01) v1(100.71,81.66) v1(100.99,66.19) v1(100.97,63.88) v1(100.97,48.26) v1(100.97,26.04) v1(100.97,23.49) v1(101.6,87.63) v1(101.6,41.27) v1(101.73,110.74) v1(102.24,46.99) v1(102.24,24.77) v1(102.49,66.42) v1(102.49,64.01) v1(102.62,53.85) v1(102.74,61.09) v1(102.74,57.15) v1(102.87,88.9) v1(102.87,86.36) v1(102.87,76.45) v1(102.87,42.55) v1(102.87,40.01) v1(103.25,136.53) v1(103.5,48.26) v1(103.5,26.04) v1(103.5,23.49) v1(103.73,117.09) v1(103.93,53.11) v1(104.01,56.39) v1(104.11,114.05) v1(104.14,81.28) v1(104.14,78.74) v1(104.52,60.45) v1(104.65,108.97) v1(104.65,66.42) v1(104.65,64.01) v1(104.65,51.44) v1(104.65,50.04) v1(104.7,55.52) v1(104.7,54.51) v1(105.41,80.01) v1(105.79,76.45) v1(105.92,60.45) v1(105.92,48.77) v1(106.68,99.06) v1(106.68,96.52) v1(106.68,81.28) v1(106.68,78.74) v1(106.68,71.12) v1(106.68,31.11) v1(106.68,28.57) v1(106.68,24.13) v1(106.68,21.59) v1(107.19,66.42) v1(107.19,53.47) v1(107.31,64.01) v1(107.44,50.67) v1(107.57,60.45) v1(107.95,97.79) v1(107.95,69.85) v1(107.95,46.35) v1(107.95,43.81) v1(107.95,29.84) v1(107.95,22.86) v1(108.08,112.52) v1(108.46,0.64) v1(108.59,49.53) v1(108.84,114.94) v1(108.84,113.54) v1(108.97,76.45) v1(109.22,99.06) v1(109.22,96.52) v1(109.22,71.12) v1(109.22,54.36) v1(109.22,45.09) v1(109.22,31.11) v1(109.22,28.57) v1(109.22,24.13) v1(109.22,21.59) v1(109.25,3.3) v1(109.35,64.01) v1(109.47,66.42) v1(109.6,136.53) v1(109.78,52.98) v1(110.18,51.84) v1(110.49,92.71) v1(110.49,90.17) v1(110.49,46.35) v1(110.49,43.81) v1(111.12,64.01) v1(111.25,66.42) v1(111.51,53.59) v1(111.76,91.44) v1(111.76,29.21) v1(111.76,26.67) v1(112.01,76.58) v1(112.27,0.64) v1(112.4,4.45) v1(112.4,1.91) v1(112.52,66.42) v1(112.52,63.88) v1(112.63,120.45) v1(112.9,62.99) v1(112.9,61.85) v1(112.9,60.45) v1(113.03,92.71) v1(113.03,90.17) v1(113.03,27.94) v1(113.41,53.59) v1(113.66,3.17) v1(113.92,108.69) v1(114.17,106.05) v1(114.17,66.55) v1(114.17,56.39) v1(114.3,29.21) v1(114.3,26.67) v1(114.55,58.29) v1(114.68,6.35) v1(114.94,136.53) v1(114.94,103.51) v1(114.94,100.97) v1(114.94,97.16) v1(114.94,94.62) v1(114.94,47.62) v1(114.94,45.09) v1(114.94,4.45) v1(114.94,1.91) v1(115.44,76.45) v1(115.44,64.01) v1(115.44,61.09) v1(115.44,60.07) v1(115.44,53.59) v1(115.57,74.8) v1(115.57,71.12) v1(115.57,68.83) v1(115.57,66.55) v1(115.57,62.48) v1(115.57,58.93) v1(115.57,56.64) v1(115.57,34.92) v1(115.57,32.38) v1(115.57,24.13) v1(115.57,21.59) v1(116.21,102.23) v1(116.21,95.89) v1(116.21,46.35) v1(116.21,15.24) v1(116.21,12.7) v1(116.84,33.66) v1(116.84,22.86) v1(117.09,63.88) v1(117.22,66.55) v1(117.47,103.51) v1(117.47,100.97) v1(117.47,97.16) v1(117.47,94.62) v1(117.47,47.62) v1(117.47,45.09) v1(117.47,13.97) v1(117.47,5.71) v1(118.11,34.92) v1(118.11,32.38) v1(118.11,24.13) v1(118.11,21.59) v1(118.36,63.88) v1(118.49,66.55) v1(118.75,15.24) v1(118.75,12.7) v1(119.38,130.81) v1(119.63,66.55) v1(119.63,63.88) v1(120.02,7.62) v2(38.48,69.22) v2(38.48,68.71) v2(38.48,61.09) v2(38.48,60.58) v2(38.73,68.96) v2(38.73,60.83) v2(38.99,69.22) v2(38.99,68.71) v2(38.99,61.09) v2(38.99,60.58) v2(40.77,58.12) v2(41.78,75.57) v2(42.67,70.26) v2(42.88,58.12) v2(43.31,75.69) v2(43.81,72.52) v2(43.81,71.12) v2(43.87,70.26) v2(45.47,72.14) v2(45.72,75.69) v2(46.48,61.09) v2(46.61,69.22) v2(46.61,68.71) v2(46.61,60.58) v2(46.85,68.95) v2(46.86,60.96) v2(47.12,69.22) v2(47.12,61.21) v2(47.12,60.58) v2(47.12,59.13) v2(47.7,67.67) v2(47.7,62.23) v2(47.88,71.63) v2(48.01,70.23) v2(48.13,75.69) v2(48.13,74.68) v2(48.17,101.77) v2(48.26,78.23) v2(48.59,64.95) v2(48.89,76.84) v2(49.4,79.5) v2(50.16,71.37) v2(50.57,67.21) v2(50.57,65.33) v2(50.57,64.67) v2(50.57,62.79) v2(50.67,80.65) v2(51.18,79.38) v2(51.44,71.63) v2(51.82,81.79) v2(52.54,69.37) v2(52.54,68.35) v2(52.58,80.77) v2(53.05,68.86) v2(53.09,83.06) v2(53.56,69.37) v2(53.56,68.35) v2(54.1,82.17) v2(105.04,120.53) v2(105.04,119.88) v2(105.48,120.53) v2(105.48,119.88) v2(105.51,115.37) v2(105.84,117.3) v2(105.94,115.37) v2(106.17,117.3) v2(107.76,59.69) v2(107.76,58.69) v2(107.76,58.19) v2(108.41,60.34) v2(108.91,60.34) v2(109.42,60.32) v2(109.91,60.34) v2(110.41,60.34) v2(110.91,60.34) v2(111.4,60.33) v2(111.91,60.35) v2(112.54,59.7) v2(112.54,58.69) v2(112.55,58.19) v2(112.56,57.69) v2(115.09,109.88) v3(4.42,104.5) v3(32.64,18.57) v3(33.02,18.21) v3(34.24,24.49) v3(34.54,23.88) v3(35.94,99.7) v3(36.45,100.33) v3(38.1,11.84) v3(38.35,98.3) v3(38.79,10.9) v3(38.86,98.81) v3(39.24,23.62) v3(39.45,14.33) v3(39.55,16.56) v3(39.5,15.42) v3(39.62,24.26) v3(39.88,24.89) v3(40.36,16.54) v3(40.41,14.33) v3(42.09,114.94) v3(42.21,115.62) v3(42.93,7.37) v3(44.2,7.87) v3(45.85,9.27) v3(51.94,6.6) v3(52.83,7.24) v3(54.36,8.66) v3(54.76,106.4) v3(55.45,106.27) v3(55.96,8.15) v3(56.64,23.72) v3(57.12,25.55) v3(66.55,119.25) v3(66.73,111.73) v3(66.73,110.39) v3(67.31,111.06) v3(67.92,111.76) v3(67.89,110.39) v3(67.97,13.11) v3(74.93,16.66) v3(77.39,71.96) v3(77.37,58.34) v3(80.54,71.96) v3(80.59,58.37) v3(82.14,9.78) v3(83.69,83.06) v3(83.69,78.74) v3(83.69,74.68) v3(84.86,72.08) v3(84.86,71.2) v3(85.12,16.38) v3(85.47,85.34) v3(85.62,72.08) v3(85.62,71.2) v3(85.7,14.55) v3(86.23,81.79) v3(86.23,76.96) v3(87.25,76.07) v3(87.25,73.66) v3(87.38,83.19) v3(87.63,85.73) v3(89.31,9.8) v3(90.04,85.73) v3(90.04,83.19) v3(90.17,76.07) v3(90.32,120.37) v3(90.3,73.66) v3(90.93,5.46) v3(90.93,3.68) v3(91.21,119.74) v3(91.31,7.62) v3(91.31,6.73) v3(91.44,4.6) v3(91.74,7.19) v3(91.95,5.46) v3(91.95,3.68) v3(92.2,85.73) v3(92.2,7.62) v3(92.2,6.73) v3(92.33,83.19) v3(93.22,75.57) v3(93.85,74.04) v3(94.74,85.73) v3(95,83.19) v3(96.9,83.19) v3(97.03,85.73) v3(98.68,85.22) v3(99.57,84.2) v3(100.46,99.19) v3(100.46,97.54) v3(100.48,98.37) v3(100.79,57.25) v3(100.79,55.8) v3(100.97,121.54) v3(100.97,120.52) v3(101.17,59.63) v3(101.19,58.84) v3(101.25,56.53) v3(101.35,99.19) v3(101.35,97.54) v3(101.37,98.37) v3(101.63,57.22) v3(101.73,55.82) v3(101.85,105.54) v3(101.85,104.72) v3(102.13,109.6) v3(102.11,84.2) v3(102.24,99.19) v3(102.24,97.54) v3(102.26,98.37) v3(102.49,81.66) v3(102.87,108.33) v3(103.15,99.21) v3(103.15,98.35) v3(103.15,97.51) v3(103.63,107.32) v3(104.52,84.2) v3(105.16,81.66) v3(105.92,110.36) v3(106.55,109.6) v3(106.68,84.33) v3(107.06,124.94) v3(107.34,123.62) v3(107.87,104.6) v3(107.95,103.25) v3(108.2,105.28) v3(108.2,81.66) v3(108.43,121.67) v3(108.46,120.6) v3(108.56,105.97) v3(109.22,84.2) v3(110.74,81.66) v3(112.09,127.06) v3(112.12,125.98) v3(112.07,118.18) v3(112.07,117.04) v3(113.34,118.18) v3(113.36,127.06) v3(113.39,125.99) v3(113.39,117.02) v3(114.17,84.2) v3(114.43,81.66) v3(116.33,84.33) v3(116.33,81.41) v3(116.64,110.54) v3(117.27,110.92) v3(117.62,127.08) v3(117.6,125.98) v3(117.59,118.18) v3(117.59,117.04) v3(118.11,84.33) v3(118.24,81.41) v3(118.85,117.04) v3(118.89,127.08) v3(118.91,126.01) v3(118.86,118.18) v3(119.51,81.53) v3(119.63,84.33) v5(90.04,60.71) v5(90.53,65.71) v5(90.53,64.19) v5(91.52,62.71) v5(92.02,67.18) v5(92,62.71) v5(93.52,67.21) v5(94.01,67.18) v5(94.01,62.71) v5(94.69,64.7) v5(94.7,64.2) v5(94.7,63.7) v5(95,65.71) v5(95,64.72) v5(95,64.21) v5(95,63.7) v5(95.12,60.58) v6(40.3,67.4) v6(40.3,66.4) v6(40.3,64.4) v6(40.3,63.4) v6(40.3,62.4) v6(41.3,66.4) v6(41.3,65.4) v6(41.3,64.4) v6(41.3,63.4) v6(42.3,66.4) v6(42.3,65.4) v6(42.3,64.4) v6(42.3,63.4) v6(42.3,62.4) v6(43.3,67.4) v6(43.3,66.4) v6(43.3,65.4) v6(43.3,64.4) v6(43.3,63.4) v6(43.3,62.4) v6(44.3,66.4) v6(44.3,65.4) v6(44.3,64.4) v6(44.3,63.4) v6(44.3,62.4) v6(109.14,58.95) v6(109.14,57.94) v6(109.14,56.92) v6(110.16,58.95) v6(110.16,57.94) v6(110.16,56.92) v6(111.17,58.95) v6(111.17,57.94) v6(111.17,56.92) v6(118.62,87.78) v6(118.62,87.02) v6(118.62,86.13) v6(118.62,85.37) v6(118.62,80.54) v6(118.62,79.78) v6(118.62,79.02) v6(118.61,78.26) v6(118.62,70.04) v6(118.62,69.15) v6(118.62,68.26) v6(118.62,67.5) v6(118.62,62.76) v6(118.62,62) v6(118.62,61.24) v6(118.62,60.48) v6(119.38,87.78) v6(119.38,87.02) v6(119.38,86.13) v6(119.38,85.37) v6(119.38,80.54) v6(119.38,79.78) v6(119.38,79.02) v6(119.37,78.26) v6(119.38,70.04) v6(119.38,69.15) v6(119.38,68.26) v6(119.38,67.5) v6(119.38,62.76) v6(119.38,62) v6(119.38,61.24) v6(119.38,60.48) v6(120.14,87.78) v6(120.14,87.02) v6(120.14,86.13) v6(120.14,85.37) v6(120.14,80.54) v6(120.14,79.78) v6(120.14,79.02) v6(120.14,78.2) v6(120.14,70.04) v6(120.14,69.15) v6(120.14,68.26) v6(120.14,67.5) v6(120.14,62.76) v6(120.14,62) v6(120.14,61.24) v6(120.14,60.48) v7(40.74,105.54) v7(41.56,106.35) v7(41.56,104.72) v7(42.37,105.54) v7(42.59,107.38) v7(42.59,103.69) v7(42.82,107.92) v7(43.4,106.57) v7(43.4,104.5) v7(43.62,108.42) v7(43.62,102.66) v7(44.43,107.6) v7(44.43,105.54) v7(44.43,103.47) v7(44.65,109.45) v7(44.65,101.63) v7(45.47,108.63) v7(45.47,106.57) v7(45.47,104.5) v7(45.47,102.44) v7(45.49,100.79) v7(45.82,110.46) v7(45.92,100.99) v7(46.28,109.45) v7(46.28,101.63) v7(46.5,107.6) v7(46.5,105.54) v7(46.5,103.47) v7(47.31,108.42) v7(47.31,102.66) v7(47.53,106.57) v7(47.53,104.5) v7(47.9,108.41) v7(48.34,107.38) v7(48.34,103.69) v7(48.56,105.54) v7(49.38,106.35) v7(49.38,104.72) v7(49.91,106.1) v8(33.8,91.58) v8(33.9,89.38) v8(34.1,92.78) v8(35,88.48) v8(37,88.48) v8(37.9,92.78) v8(38.1,89.38) v8(38.2,91.58)
ALARM: length 10.2
  TOP w0.102: 44.9,60.35 44.9,60.35 44.9,60.09 44.9,60.09 44.9,59.23 ; 44.9,60.47 44.89,60.47 44.89,60.72 44.9,60.73
  TOP w0.127: 44.9,60.47 44.9,60.35 ; U1.B29 44.9,60.73
  TOP w0.152: 44.9,59.23 44.9,58.87 44.87,58.84 44.87,57.14 44.87,57.14 44.87,56.91 44.58,56.61 44.58,51.69 PP1.1
ATT_LE: length 56.5
  L6_PWR w0.152: v2(112.56,56.69) 112.56,57.18 112.91,57.54 112.91,57.59 113.66,58.34 113.66,63.23 113.03,63.87 113.03,83.13 97.16,99.01 92.46,99.01 v1(90.92,100.55)
CLKIN0N: length 3.1
  TOP w0.152: C100.2 52.23,102.33 51.2,103.35 50.83,103.35 U16.29
CLKIN0P: length 3.1
  TOP w0.152: C101.2 51.95,102.07 51.05,102.97 50.68,102.97 50.11,103.54 U16.28
CLKIN1P: length 3
  TOP w0.254: U16.25 48.88,102.48 49.45,101.9
  TOP w0.305: 49.45,101.9 49.66,101.7 49.66,100.84 C79.2
CLKOUT0N: length 34.9
  TOP w0.152: R59.1 34.09,108.05 33.34,108.8 33.34,117.13 42.48,126.28 42.48,132.28 42.05,132.72 J3.1
CLKOUT0P: length 35.3
  TOP w0.152: J2.1 43.38,132.72 42.82,132.16 42.82,126.14 33.68,116.99 33.68,108.94 34.36,108.26 R58.1
CLKOUT6P: length 25.8
  TOP w0.305: J5.1 58.83,132.59 48.84,122.6 R50.1
CLKOUT8N: length 4.3
  TOP w0.152: U16.54 43.11,109.92 42.56,110.48 42.55,110.48 41.33,111.69 41.33,111.73 41.31,111.75 R91.1 40.85,111.75 R276.1
CLKOUT8P: length 4.3
  TOP w0.152: U16.53 43.46,110.02 43.39,110.02 43.39,110.04 42.68,110.76 42.66,110.76 41.61,111.8 R55.1 41.6,112.48 R275.1
CLKOUT_0N: length 6.7
  TOP w0.152: R59.2 35.51,106.05 R56.1 36.04,106.05 38.28,103.81 39.03,103.81 39.28,104.06 39.39,104.06 U16.2
CLKOUT_0P: length 6.1
  TOP w0.152: R58.2 36.37,106.78 R57.1 36.37,106.27 36.34,106.24 38.42,104.15 38.89,104.15 39.04,104.31 39.04,104.42 U16.1
CLKOUT_6P: length 2.9
  TOP w0.305: 46.05,111.43 46.05,111.46 R50.2
CLOCK1: length 2.5
  TOP w0.305: R63.2 R105.1 51.69,98.81 C79.1
CLOCKIN: length 10.3
  TOP w0.305: R63.1 R130.1 56.29,98.81 59.84,102.36 J12.1
CP1: length 7
  TOP w0.305: R273.1 55.6,107.42 54.17,107.42 C177.1 C300.1 53.25,108.21 51.76,106.72 51.25,106.72 U16.34
CPLD_CLK: length 1.2
  TOP w0.305: R53.1 69.65,118.31 69.72,118.24
DA0N: length 53.3
  TOP w0.127: U1.A27 42.2,60.13
  TOP w0.152: v1(7.11,49.15) 7.11,49.39 7.49,49.76 10.52,49.76 11.3,50.55 13.74,50.55 14.01,50.82 14.01,51.3 14.12,51.41 14.28,51.41 14.39,51.3 14.39,50.82 14.67,50.55 15.06,50.55 15.33,50.82 15.33,51.3 15.45,51.41 15.6,51.41 15.71,51.3 15.71,50.82 15.99,50.55 16.38,50.55 16.65,50.82 16.65,51.3 16.77,51.41 16.92,51.41 17.04,51.3 17.04,50.82 17.31,50.55 17.7,50.55 17.98,50.82 17.98,51.3 18.09,51.41 18.25,51.41 18.36,51.3 18.36,50.82 18.63,50.55 19.02,50.55 19.3,50.82 19.3,51.3 19.41,51.41 19.57,51.41 19.68,51.3 19.68,50.82 19.95,50.55 20.34,50.55 20.62,50.82 20.62,51.3 20.73,51.41 20.89,51.41 21,51.3 21,50.82 21.27,50.55 21.66,50.55 21.94,50.82 21.94,51.3 22.05,51.41 23.01,51.41 23.88,50.55 35.94,50.55 42.44,57.05 42.44,59.89 42.2,60.13
  BOTTOM w0.152: J13.165 6.29,49.97 v1(7.11,49.15)
DA0P: length 53.2
  TOP w0.127: U1.B24 41.9,60.21 41.91,60.2 41.91,60.03 41.95,59.99
  TOP w0.152: v1(7.11,50.8) 7.56,50.35 7.56,50.34 7.87,50.04 10.4,50.04 11.19,50.83 13.62,50.83 13.73,50.94 13.73,51.41 14.01,51.69 14.4,51.69 14.67,51.41 14.67,50.94 14.79,50.83 14.94,50.83 15.05,50.94 15.05,51.41 15.33,51.69 15.72,51.69 15.99,51.41 15.99,50.94 16.11,50.83 16.26,50.83 16.38,50.94 16.38,51.41 16.65,51.69 17.04,51.69 17.32,51.41 17.32,50.94 17.43,50.83 17.58,50.83 17.7,50.94 17.7,51.41 17.97,51.69 18.36,51.69 18.64,51.41 18.64,50.94 18.75,50.83 18.91,50.83 19.02,50.94 19.02,51.41 19.29,51.69 19.68,51.69 19.96,51.41 19.96,50.94 20.07,50.83 20.23,50.83 20.34,50.94 20.34,51.41 20.61,51.69 21,51.69 21.28,51.41 21.28,50.94 21.39,50.83 21.55,50.83 21.66,50.94 21.66,51.41 21.93,51.69 23.13,51.69 23.99,50.83 35.83,50.83 42.16,57.16 42.16,59.77 41.95,59.99
  BOTTOM w0.152: v1(7.11,50.8) 6.79,50.47 J13.163
DA1N: length 53.3
  TOP w0.127: U1.A26 41.55,60.55 41.55,60.46 41.57,60.44 41.57,60.36 41.58,60.35 41.58,60.33
  TOP w0.152: 41.58,60.33 41.58,59.96 41.71,59.83 41.71,59.6 41.71,57.77 40.93,57 40.23,57 35.69,52.45 34.2,52.45 33.84,52.81 33.69,52.81 33.57,52.7 33.57,52.17 33.3,51.89 32.91,51.89 32.64,52.17 32.64,52.7 32.52,52.81 32.37,52.81 32.25,52.7 32.25,52.17 31.98,51.89 31.59,51.89 31.31,52.17 31.31,52.7 31.2,52.81 31.04,52.81 30.93,52.7 30.93,52.17 30.66,51.89 30.27,51.89 29.99,52.17 29.99,52.7 29.88,52.81 29.72,52.81 29.61,52.7 29.61,52.17 29.34,51.89 28.95,51.89 28.67,52.17 28.67,52.7 28.56,52.81 28.4,52.81 28.29,52.7 28.29,52.17 28.07,51.94 27.58,51.94 27.35,52.17 27.35,52.56 27.13,52.78 24.41,52.78 23.98,52.35 9.09,52.35 8.81,52.07 7.62,52.07 7.37,51.82 6.1,51.82 5.87,51.59 3.51,51.59 v1(3.21,51.28)
  BOTTOM w0.152: v1(3.21,51.28) 3.51,51.59 4.12,51.59 4.23,51.48 J13.159
DA1P: length 53.4
  TOP w0.127: 41.3,60.33 41.3,60.33 U1.B23
  TOP w0.152: v1(3.21,52.17) 3.51,51.87 5.75,51.87 5.98,52.1 7.25,52.1 7.5,52.35 8.7,52.35 8.98,52.63 23.87,52.63 24.3,53.06 27.25,53.06 27.63,52.68 27.63,52.28 27.69,52.22 27.95,52.22 28.01,52.28 28.01,52.81 28.29,53.09 28.68,53.09 28.95,52.81 28.95,52.28 29.06,52.17 29.22,52.17 29.33,52.28 29.33,52.81 29.61,53.09 30,53.09 30.27,52.81 30.27,52.28 30.38,52.17 30.54,52.17 30.65,52.28 30.65,52.81 30.93,53.09 31.32,53.09 31.59,52.81 31.59,52.28 31.71,52.17 31.86,52.17 31.97,52.28 31.97,52.81 32.25,53.09 32.64,53.09 32.91,52.81 32.91,52.28 33.03,52.17 33.18,52.17 33.3,52.28 33.3,52.81 33.57,53.09 33.96,53.09 34.32,52.73 35.57,52.73 40.12,57.28 40.82,57.28 41.43,57.89 41.43,59.72 41.3,59.84 41.3,60.33
  BOTTOM w0.152: J13.157 4.23,51.98 4.12,51.87 3.51,51.87 v1(3.21,52.17)
DA2N: length 53.4
  TOP w0.127: U1.B22 40.7,60.67 40.7,60.67 40.7,60.38 40.71,60.38 40.71,59.87 40.66,59.82
  TOP w0.152: v1(7.15,52.63) 7.45,52.93 8.1,52.93 8.89,53.72 9.27,53.72 9.51,53.97 9.51,53.99 9.59,54.08 9.71,54.08 9.79,53.99 9.79,53.61 10.04,53.37 10.38,53.37 10.63,53.61 10.63,53.64 10.71,53.72 11.43,53.72 12.62,54.91 13.27,54.91 13.38,54.8 13.38,54.07 13.65,53.8 14.04,53.8 14.32,54.07 14.32,54.8 14.43,54.91 14.59,54.91 14.7,54.8 14.7,54.07 14.97,53.8 15.36,53.8 15.64,54.07 15.64,54.8 15.75,54.91 15.91,54.91 16.02,54.8 16.02,54.07 16.29,53.8 16.68,53.8 16.96,54.07 16.96,54.8 17.07,54.91 17.23,54.91 17.34,54.8 17.34,54.07 17.61,53.8 18,53.8 18.28,54.07 18.28,54.8 18.39,54.91 18.55,54.91 18.66,54.8 18.66,54.07 18.94,53.8 19.33,53.8 19.6,54.07 19.6,54.8 19.71,54.91 19.87,54.91 19.98,54.8 19.98,54.07 20.26,53.8 20.65,53.8 20.92,54.07 20.92,54.8 21.03,54.91 21.19,54.91 21.3,54.8 21.3,54.07 21.58,53.8 21.97,53.8 22.53,54.36 35.75,54.36 40.57,59.17 40.57,59.72 40.66,59.81 40.66,59.82
  BOTTOM w0.152: v1(7.15,52.63) 6.7,53.09 6.24,53.09 6.13,52.98 J13.153
DA2P: length 53.3
  TOP w0.127: 40.38,59.93 40.38,59.94 40.44,60 40.44,60.54 40.44,60.54 40.44,60.55 U1.A24
  TOP w0.152: v1(7.15,53.51) 7.45,53.21 7.99,53.21 8.77,54 9.15,54 9.23,54.08 9.23,54.11 9.48,54.36 9.82,54.36 10.07,54.11 10.07,53.73 10.15,53.64 10.27,53.64 10.35,53.73 10.35,53.76 10.59,54 11.31,54 12.51,55.19 13.38,55.19 13.66,54.92 13.66,54.19 13.77,54.08 13.93,54.08 14.04,54.19 14.04,54.92 14.31,55.19 14.7,55.19 14.98,54.92 14.98,54.19 15.09,54.08 15.25,54.08 15.36,54.19 15.36,54.92 15.63,55.19 16.02,55.19 16.3,54.92 16.3,54.19 16.41,54.08 16.57,54.08 16.68,54.19 16.68,54.92 16.95,55.19 17.34,55.19 17.62,54.92 17.62,54.19 17.73,54.08 17.89,54.08 18,54.19 18,54.92 18.28,55.19 18.66,55.19 18.94,54.92 18.94,54.19 19.05,54.08 19.21,54.08 19.32,54.19 19.32,54.92 19.6,55.19 19.99,55.19 20.26,54.92 20.26,54.19 20.37,54.08 20.53,54.08 20.64,54.19 20.64,54.92 20.92,55.19 21.31,55.19 21.58,54.92 21.58,54.19 21.69,54.08 21.85,54.08 22.41,54.64 22.95,54.64 23.18,54.86 23.46,54.86 23.69,54.64 23.97,54.64 24.2,54.86 24.48,54.86 24.71,54.64 24.99,54.64 25.21,54.86 25.49,54.86 25.72,54.64 26,54.64 26.23,54.86 26.51,54.86 26.74,54.64 27.02,54.64 27.25,54.86 27.53,54.86 27.75,54.64 28.03,54.64 28.26,54.86 28.54,54.86 28.77,54.64 35.64,54.64 40.29,59.29 40.29,59.84 40.38,59.93
  BOTTOM w0.152: J13.151 6.13,53.48 6.24,53.37 7.01,53.37 v1(7.15,53.51)
DA3N: length 53.2
  TOP w0.127: U1.B21 40.1,60.05
  TOP w0.152: v1(7.15,54.29) 7.45,54.59 8.12,54.59 9.29,55.75 11,55.75 11.25,56.01 24.65,56.01 24.78,55.88 24.78,55.67 25.05,55.4 25.44,55.4 25.72,55.67 25.72,56.51 25.83,56.62 25.99,56.62 26.1,56.51 26.1,55.67 26.37,55.4 26.76,55.4 27.04,55.67 27.04,56.51 27.15,56.62 27.31,56.62 27.42,56.51 27.42,55.67 27.69,55.4 28.08,55.4 28.36,55.67 28.36,56.51 28.47,56.62 28.63,56.62 28.74,56.51 28.74,55.67 29.02,55.4 29.41,55.4 29.68,55.67 29.68,56.51 29.79,56.62 29.95,56.62 30.06,56.51 30.06,55.67 30.34,55.4 30.73,55.4 31,55.67 31,56.51 31.11,56.62 31.27,56.62 31.38,56.51 31.38,55.67 31.66,55.4 32.05,55.4 32.32,55.67 32.32,56.51 32.43,56.62 32.59,56.62 32.7,56.51 32.7,55.67 32.98,55.4 33.37,55.4 33.64,55.67 33.64,56.51 33.75,56.62 33.91,56.62 34.02,56.51 34.02,55.67 34.3,55.4 34.82,55.4 35.43,56.01 36.04,56.01 39.98,59.95 40,59.95 40.1,60.05
  BOTTOM w0.152: J13.147 6.13,54.48 6.24,54.59 6.85,54.59 v1(7.15,54.29)
DA3P: length 53.2
  TOP w0.127: U1.A23 39.8,60.59 39.8,60.16
  TOP w0.152: 39.8,60.16 35.93,56.29 34.96,56.29 34.68,56.01 34.68,55.79 34.57,55.68 34.41,55.68 34.3,55.79 34.3,56.62 34.03,56.9 33.64,56.9 33.36,56.62 33.36,55.79 33.25,55.68 33.09,55.68 32.98,55.79 32.98,56.62 32.71,56.9 32.32,56.9 32.04,56.62 32.04,55.79 31.93,55.68 31.77,55.68 31.66,55.79 31.66,56.62 31.39,56.9 31,56.9 30.72,56.62 30.72,55.79 30.61,55.68 30.45,55.68 30.34,55.79 30.34,56.62 30.07,56.9 29.68,56.9 29.4,56.62 29.4,55.79 29.29,55.68 29.13,55.68 29.02,55.79 29.02,56.62 28.74,56.9 28.36,56.9 28.08,56.62 28.08,55.79 27.97,55.68 27.81,55.68 27.7,55.79 27.7,56.62 27.42,56.9 27.03,56.9 26.76,56.62 26.76,55.79 26.65,55.68 26.49,55.68 26.38,55.79 26.38,56.62 26.1,56.9 25.71,56.9 25.44,56.62 25.44,55.79 25.33,55.68 25.17,55.68 25.06,55.79 25.06,56.62 24.78,56.9 24.39,56.9 24.12,56.62 24.12,56.4 24.01,56.29 11.14,56.29 10.88,56.03 9.17,56.03 8,54.87 7.45,54.87 v1(7.15,55.17)
  BOTTOM w0.152: v1(7.15,55.17) 6.85,54.87 6.24,54.87 6.13,54.98 J13.145
